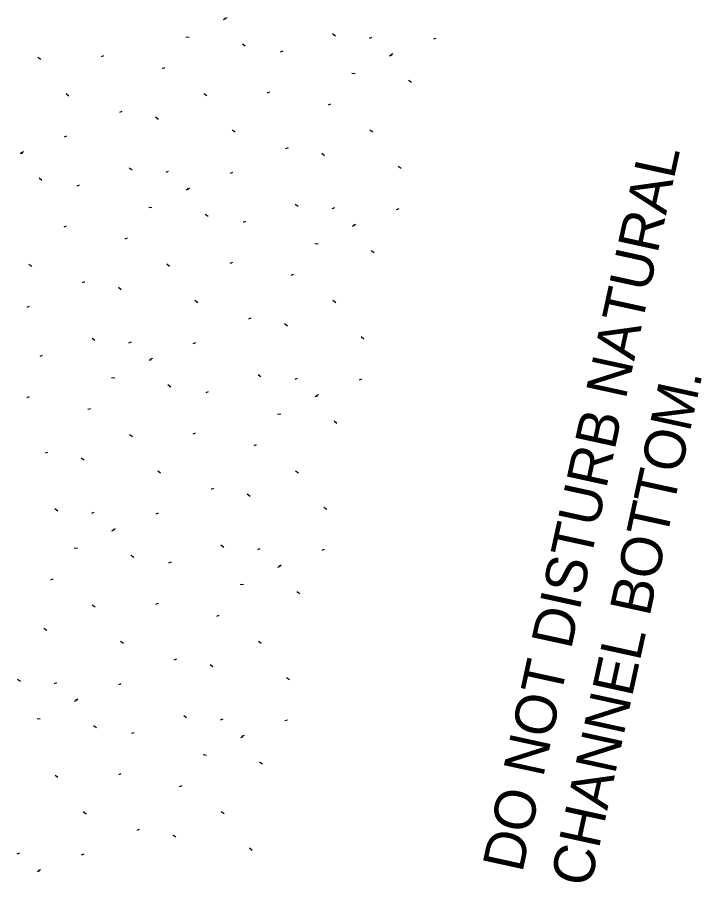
# Model space of a CAD drawing. Extents: x 2126110 to 2128246, y 1804858 to 1811658.
# Drawn here: x 2126685.9 to 2126769.4, y 1805556.8 to 1805662.4 of the extents above; entities that cross this region are included whole.
import ezdxf

# ---------------------------------------------------------------- set-up
doc = ezdxf.new("R2010")
doc.units = 0
doc.layers.add('1', color=7, linetype='Continuous')

msp = doc.modelspace()

# ---------------------------------------------------------------- linework, layer by layer
at = {"layer": '1'}
for p, q in [((2126711.05, 1805662.1), (2126711.35, 1805662.21)), ((2126711.19, 1805662.25), (2126711.49, 1805662.36)), ((2126706.46, 1805660), (2126706.86, 1805659.95)), ((2126724.7, 1805660.07), (2126724.35, 1805660.33)), ((2126728.86, 1805659.82), (2126729.16, 1805659.94)), ((2126736.71, 1805659.72), (2126737.01, 1805659.84)), ((2126713.71, 1805658.83), (2126713.35, 1805659.09)), ((2126718.01, 1805658.17), (2126718.31, 1805658.29)), ((2126688.75, 1805657.2), (2126688.4, 1805657.46)), ((2126696.16, 1805657.58), (2126696.46, 1805657.7)), ((2126731.31, 1805657.67), (2126731.61, 1805657.78)), ((2126731.45, 1805657.82), (2126731.75, 1805657.94)), ((2126703.59, 1805656.12), (2126703.89, 1805656.24)), ((2126726.72, 1805655.57), (2126727.12, 1805655.53)), ((2126733.97, 1805654.41), (2126733.62, 1805654.66)), ((2126692.2, 1805652.76), (2126691.84, 1805653.02)), ((2126709.01, 1805652.77), (2126708.66, 1805653.03)), ((2126716.42, 1805653.15), (2126716.72, 1805653.27)), ((2126698.4, 1805650.8), (2126698.69, 1805650.92)), ((2126723.86, 1805651.7), (2126724.15, 1805651.81)), ((2126703.12, 1805649.92), (2126702.77, 1805650.18)), ((2126691.64, 1805647.8), (2126691.94, 1805647.91)), ((2126712.46, 1805648.34), (2126712.11, 1805648.59)), ((2126729.28, 1805648.34), (2126728.92, 1805648.6)), ((2126686.25, 1805645.75), (2126686.55, 1805645.86)), ((2126686.38, 1805645.9), (2126686.68, 1805646.01)), ((2126718.66, 1805646.38), (2126718.96, 1805646.49)), ((2126723.38, 1805645.49), (2126723.03, 1805645.75)), ((2126699.9, 1805643.72), (2126699.55, 1805643.98)), ((2126704.06, 1805643.47), (2126704.35, 1805643.59)), ((2126732.72, 1805643.91), (2126732.37, 1805644.17)), ((2126688.9, 1805642.48), (2126688.55, 1805642.74)), ((2126711.9, 1805643.37), (2126712.2, 1805643.49)), ((2126693.21, 1805641.82), (2126693.5, 1805641.94)), ((2126706.51, 1805641.32), (2126706.81, 1805641.43)), ((2126706.65, 1805641.47), (2126706.95, 1805641.59)), ((2126720.16, 1805639.29), (2126719.81, 1805639.55)), ((2126701.92, 1805639.22), (2126702.32, 1805639.18)), ((2126709.17, 1805638.06), (2126708.81, 1805638.31)), ((2126724.32, 1805639.04), (2126724.62, 1805639.16)), ((2126732.17, 1805638.94), (2126732.47, 1805639.06)), ((2126713.47, 1805637.4), (2126713.77, 1805637.51)), ((2126726.91, 1805637.04), (2126727.21, 1805637.16)), ((2126691.62, 1805636.8), (2126691.91, 1805636.92)), ((2126726.77, 1805636.89), (2126727.07, 1805637.01)), ((2126699.05, 1805635.35), (2126699.35, 1805635.46)), ((2126722.18, 1805634.79), (2126722.58, 1805634.75)), ((2126729.43, 1805633.63), (2126729.08, 1805633.89)), ((2126687.66, 1805631.98), (2126687.3, 1805632.24)), ((2126704.47, 1805631.99), (2126704.12, 1805632.25)), ((2126711.88, 1805632.37), (2126712.18, 1805632.49)), ((2126719.32, 1805630.92), (2126719.61, 1805631.03)), ((2126693.86, 1805630.03), (2126694.15, 1805630.14)), ((2126698.58, 1805629.14), (2126698.23, 1805629.4)), ((2126707.92, 1805627.56), (2126707.57, 1805627.82)), ((2126724.74, 1805627.56), (2126724.38, 1805627.82)), ((2126687.1, 1805627.02), (2126687.4, 1805627.14)), ((2126714.12, 1805625.6), (2126714.42, 1805625.71)), ((2126718.84, 1805624.72), (2126718.49, 1805624.97)), ((2126695.36, 1805622.94), (2126695.01, 1805623.2)), ((2126699.52, 1805622.69), (2126699.81, 1805622.81)), ((2126707.36, 1805622.59), (2126707.66, 1805622.71)), ((2126728.18, 1805623.13), (2126727.83, 1805623.39)), ((2126688.67, 1805621.05), (2126688.96, 1805621.16)), ((2126701.97, 1805620.54), (2126702.27, 1805620.66)), ((2126702.11, 1805620.69), (2126702.41, 1805620.81)), ((2126697.38, 1805618.44), (2126697.78, 1805618.4)), ((2126715.62, 1805618.51), (2126715.27, 1805618.77)), ((2126719.78, 1805618.26), (2126720.08, 1805618.38)), ((2126727.63, 1805618.16), (2126727.92, 1805618.28)), ((2126704.63, 1805617.28), (2126704.27, 1805617.54)), ((2126687.08, 1805616.02), (2126687.37, 1805616.14)), ((2126708.93, 1805616.62), (2126709.23, 1805616.73)), ((2126722.23, 1805616.11), (2126722.53, 1805616.23)), ((2126722.37, 1805616.26), (2126722.67, 1805616.38)), ((2126694.51, 1805614.57), (2126694.81, 1805614.68)), ((2126717.64, 1805614.01), (2126718.04, 1805613.97)), ((2126724.89, 1805612.85), (2126724.54, 1805613.11)), ((2126699.93, 1805611.21), (2126699.58, 1805611.47)), ((2126707.34, 1805611.59), (2126707.64, 1805611.71)), ((2126714.78, 1805610.14), (2126715.07, 1805610.26)), ((2126689.32, 1805609.25), (2126689.61, 1805609.36)), ((2126694.04, 1805608.37), (2126693.69, 1805608.62)), ((2126703.38, 1805606.78), (2126703.03, 1805607.04)), ((2126720.19, 1805606.79), (2126719.84, 1805607.04)), ((2126709.58, 1805604.82), (2126709.88, 1805604.94)), ((2126714.3, 1805603.94), (2126713.95, 1805604.2)), ((2126690.82, 1805602.16), (2126690.47, 1805602.42)), ((2126723.64, 1805602.35), (2126723.29, 1805602.61)), ((2126694.98, 1805601.91), (2126695.27, 1805602.03)), ((2126702.82, 1805601.81), (2126703.12, 1805601.93)), ((2126697.43, 1805599.76), (2126697.73, 1805599.88)), ((2126697.57, 1805599.91), (2126697.86, 1805600.03)), ((2126692.84, 1805597.66), (2126693.24, 1805597.62)), ((2126711.08, 1805597.73), (2126710.73, 1805597.99)), ((2126715.24, 1805597.49), (2126715.54, 1805597.6)), ((2126723.09, 1805597.38), (2126723.38, 1805597.5)), ((2126700.09, 1805596.5), (2126699.73, 1805596.76)), ((2126704.39, 1805595.84), (2126704.69, 1805595.96)), ((2126717.69, 1805595.33), (2126717.99, 1805595.45)), ((2126717.83, 1805595.49), (2126718.13, 1805595.6)), ((2126689.97, 1805593.79), (2126690.27, 1805593.91)), ((2126713.1, 1805593.23), (2126713.5, 1805593.19)), ((2126720.35, 1805592.07), (2126720, 1805592.33)), ((2126702.8, 1805590.82), (2126703.1, 1805590.93)), ((2126695.39, 1805590.43), (2126695.04, 1805590.69)), ((2126710.23, 1805589.36), (2126710.53, 1805589.48)), ((2126689.5, 1805587.59), (2126689.15, 1805587.85)), ((2126698.84, 1805586), (2126698.48, 1805586.26)), ((2126715.65, 1805586.01), (2126715.3, 1805586.27)), ((2126705.04, 1805584.04), (2126705.34, 1805584.16)), ((2126709.76, 1805583.16), (2126709.41, 1805583.42)), ((2126686.28, 1805581.38), (2126685.93, 1805581.64)), ((2126690.43, 1805581.14), (2126690.73, 1805581.25)), ((2126719.1, 1805581.57), (2126718.75, 1805581.83)), ((2126698.28, 1805581.03), (2126698.58, 1805581.15)), ((2126693.03, 1805579.13), (2126693.32, 1805579.25)), ((2126692.89, 1805578.98), (2126693.19, 1805579.1)), ((2126706.54, 1805576.95), (2126706.19, 1805577.21)), ((2126688.3, 1805576.88), (2126688.7, 1805576.84)), ((2126695.55, 1805575.72), (2126695.19, 1805575.98)), ((2126710.7, 1805576.71), (2126711, 1805576.82)), ((2126718.55, 1805576.61), (2126718.84, 1805576.72)), ((2126699.85, 1805575.06), (2126700.15, 1805575.18)), ((2126713.15, 1805574.55), (2126713.45, 1805574.67)), ((2126713.29, 1805574.71), (2126713.59, 1805574.82)), ((2126708.56, 1805572.46), (2126708.96, 1805572.41)), ((2126715.81, 1805571.29), (2126715.46, 1805571.55)), ((2126690.85, 1805569.66), (2126690.5, 1805569.91)), ((2126698.26, 1805570.04), (2126698.56, 1805570.15)), ((2126705.69, 1805568.58), (2126705.99, 1805568.7)), ((2126694.3, 1805565.22), (2126693.94, 1805565.48)), ((2126711.11, 1805565.23), (2126710.76, 1805565.49)), ((2126700.5, 1805563.26), (2126700.8, 1805563.38)), ((2126705.22, 1805562.38), (2126704.87, 1805562.64)), ((2126685.89, 1805560.36), (2126686.19, 1805560.47)), ((2126693.74, 1805560.26), (2126694.04, 1805560.37)), ((2126714.56, 1805560.79), (2126714.21, 1805561.05)), ((2126688.35, 1805558.2), (2126688.65, 1805558.32)), ((2126688.49, 1805558.36), (2126688.78, 1805558.47))]:
    msp.add_line(p, q, dxfattribs=at)

# ---------------------------------------------------------------- texts
for s, p in [('DO NOT DISTURB NATURAL ', (2126747.49, 1805557.96)), ('CHANNEL BOTTOM.', (2126755.79, 1805556.15))]:
    msp.add_text(s, height=5, rotation=77.6736, dxfattribs=at).set_placement(p)

doc.saveas('drawing.dxf')
